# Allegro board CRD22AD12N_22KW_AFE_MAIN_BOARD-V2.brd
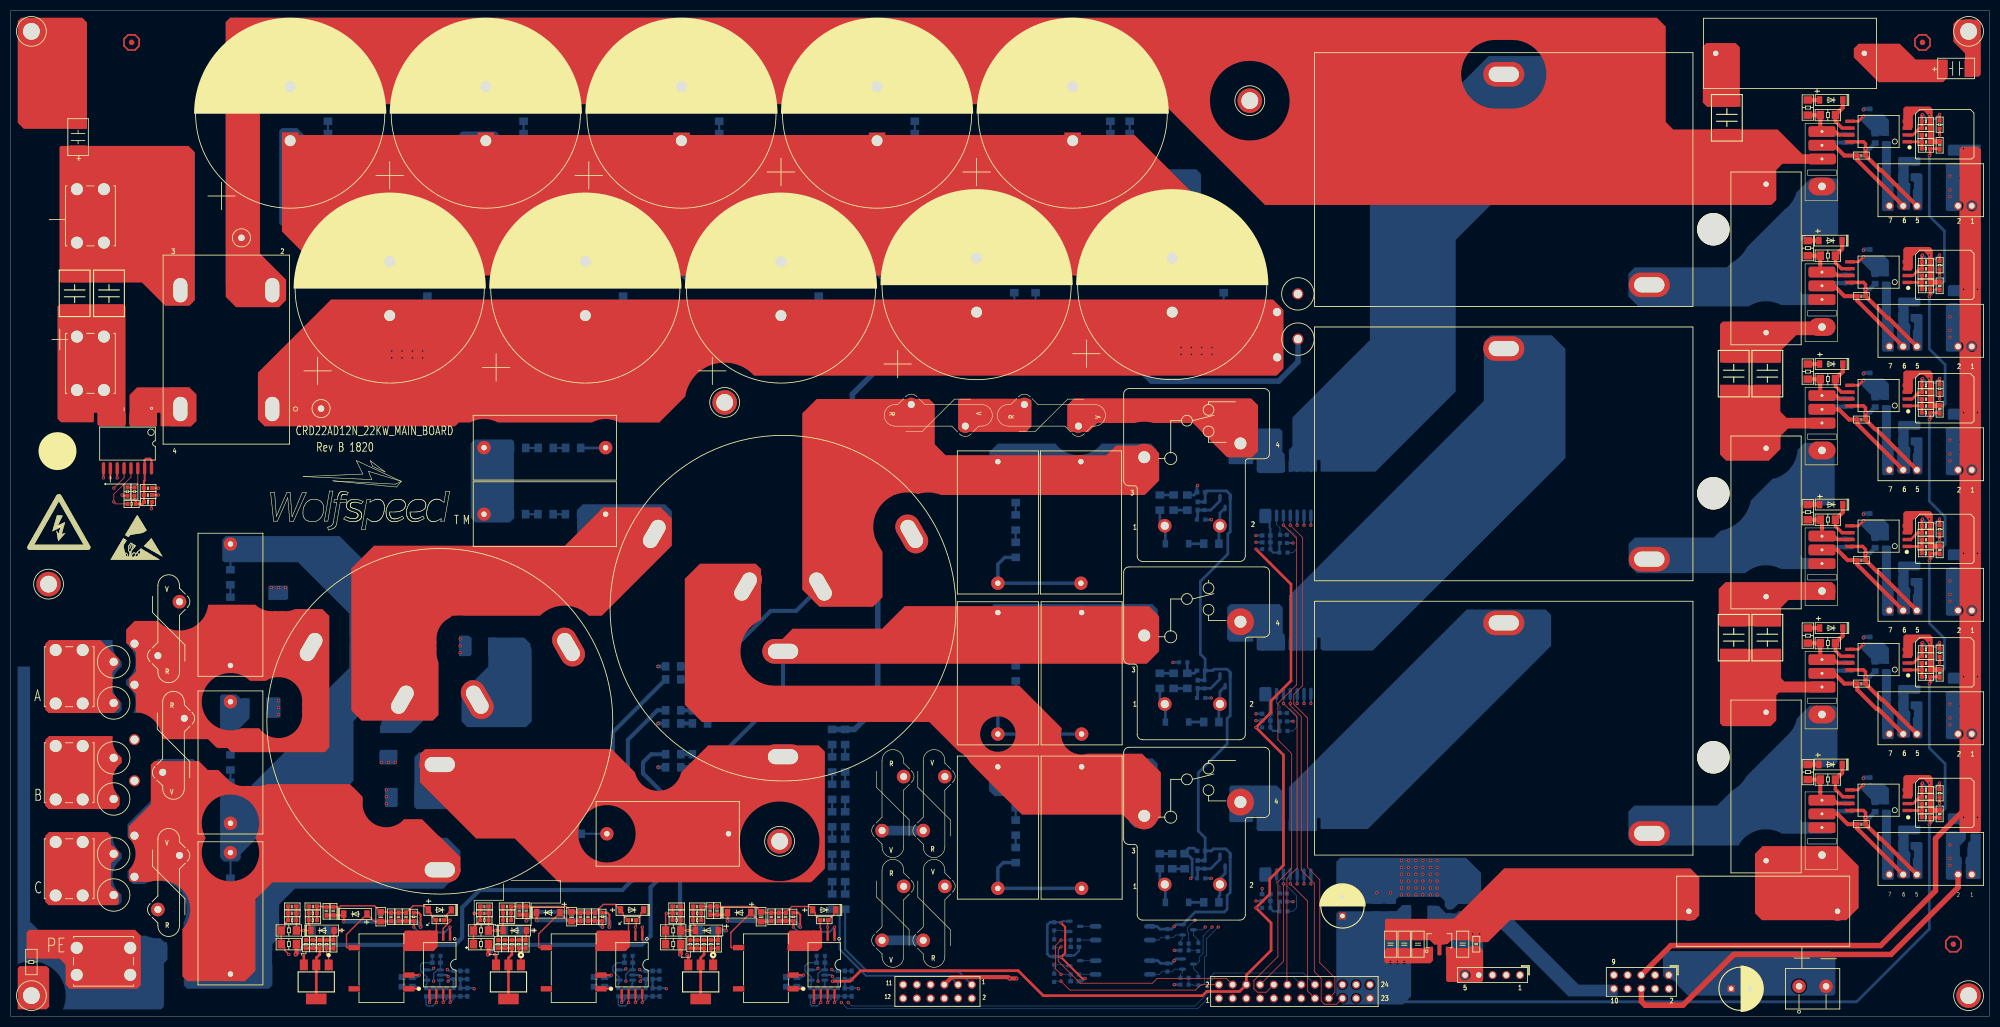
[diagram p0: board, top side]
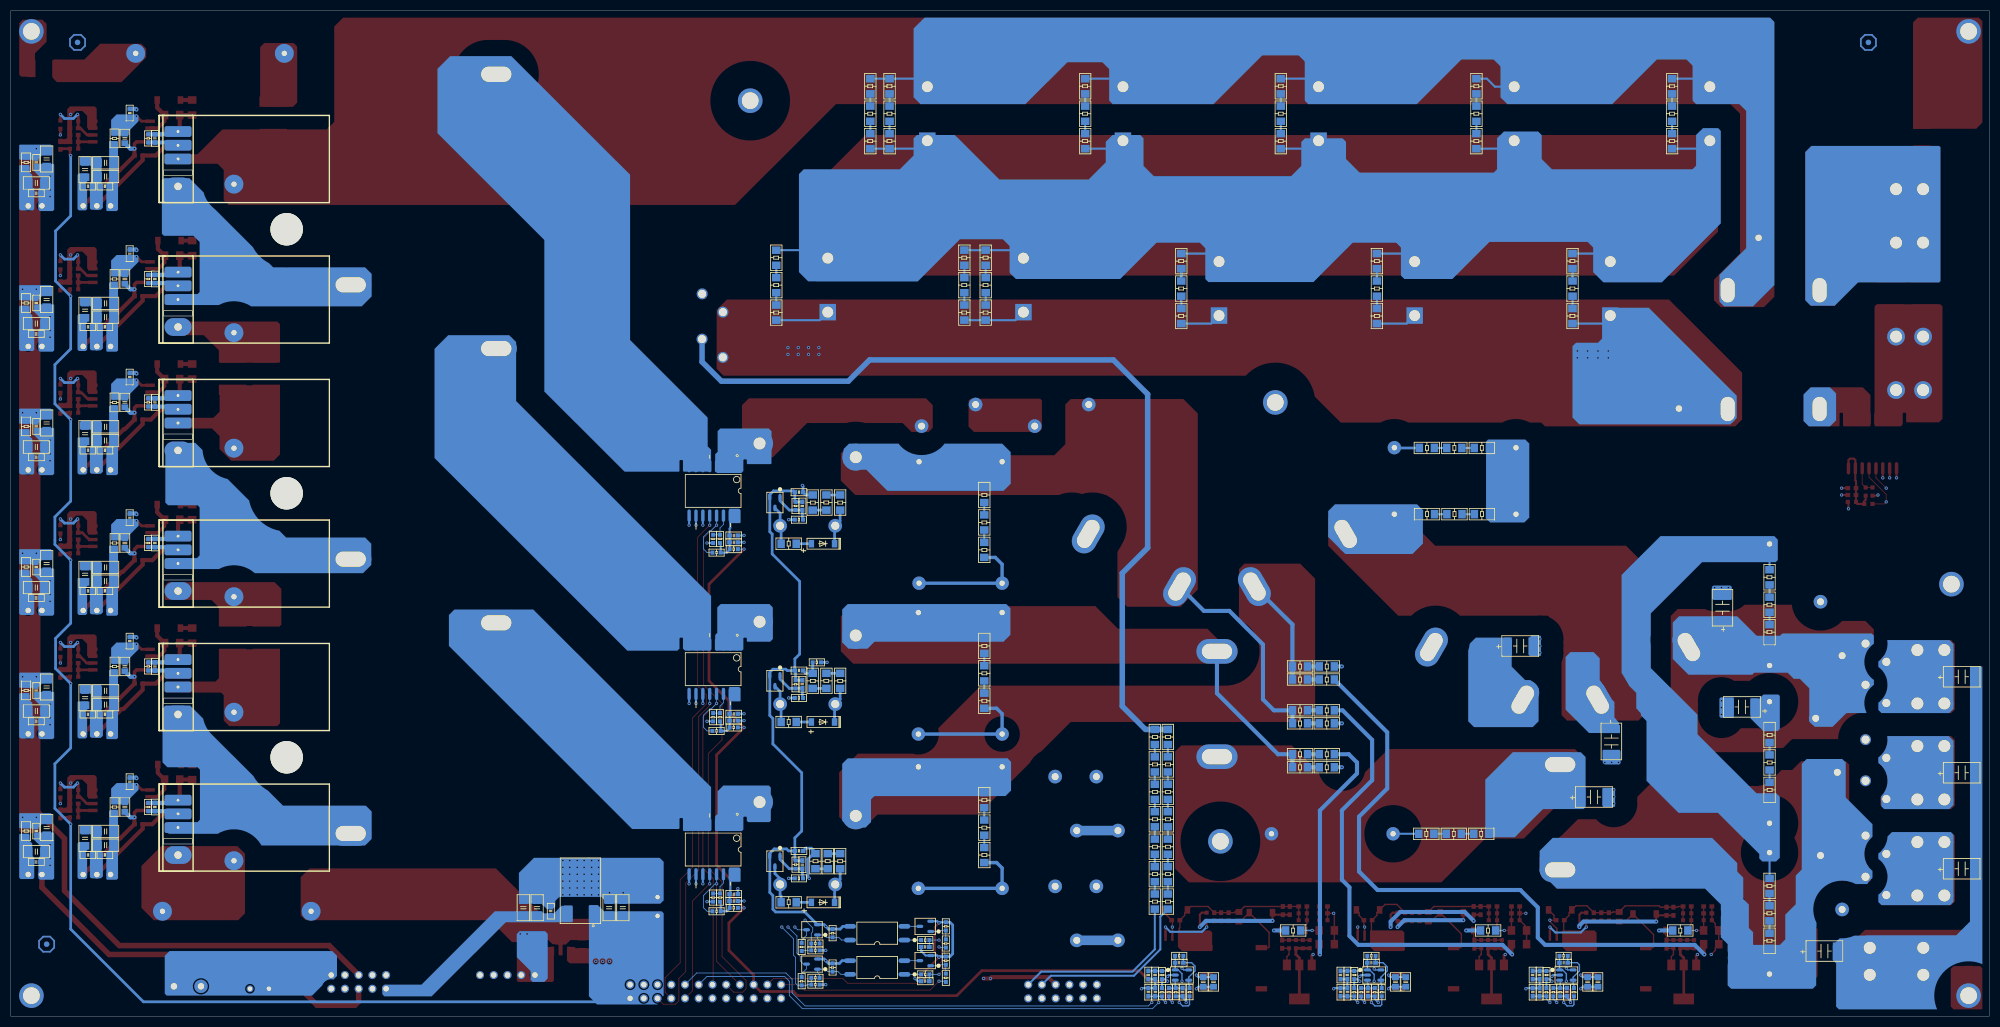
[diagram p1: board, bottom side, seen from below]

Outline 366.04 x 186.19 mm; copper layers: TOP, GND02, POWER03, BOTTOM. Coordinates in mm from the lower left corner of the outline.
Outline path: rectangle 332.45,155.71 337.75,156.71 ; rectangle 332.45,129.67 337.75,130.67 ; rectangle 332.45,106.81 337.75,107.81 ; rectangle 332.45,80.78 337.75,81.78 ; rectangle 332.45,57.92 337.75,58.92 ; rectangle 332.45,31.88 337.75,32.88 ; 0,186.19 0,0 366.04,0 366.04,186.19 0,186.19

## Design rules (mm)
net group DI: nets AGND GGND GND_EARTH IGND PGND
net group GAO: nets AC_LA AC_LA1 AC_LAP AC_LB AC_LB1 AC_LBP AC_LC AC_LC1 AC_LCP LA LB LC N17896613 N17896948 N17898200 N17898311 N17908016 N17908018 N17908020 N17908062 N17916066 N17916108 N17916243 N17920487 VPFC
net group R_DI: nets N17911032 N17911109 N17911239 N17911323 N18077724 N18077784 N179113761

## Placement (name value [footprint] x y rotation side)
C1  0.1uF  [C0603]  220.22 30.61 0 bottom
C2  1n  [C0603]  219.58 28.07 270 bottom
C3  0u1  [C0603]  196.85 6.48 0 bottom
C4  0.1uF  [C0603]  220.22 97.03 0 bottom
C5  1n  [C0603]  219.58 94.49 270 bottom
C6  0u1  [C0603]  196.85 12.83 0 bottom
C7  1n  [C0603]  339.36 38.73 270 bottom
C8  1n  [C0603]  339.36 136.53 270 bottom
C9  1n  [C0603]  339.36 87.63 270 bottom
C10  500V 680uF  [ECAP_D35P7_25]  106.3 134.75 90 top
C11  500V 680uF  [ECAP_D35P7_25]  142.49 134.75 90 top
C13  500V 680uF  [ECAP_D35P7_25]  178.69 135.38 90 top
C16  500V 680uF  [ECAP_D35P7_25]  214.88 135.38 90 top
C17  500V 680uF  [ECAP_D35P7_25]  70.1 134.75 90 top
C19  0u1  [C2220]  317.5 166.37 270 top
C20  0u1  [C2220]  318.77 119 270 top
C21  0u1  [C2220]  324.99 119 270 top
C23  500V 680uF  [ECAP_D35P7_25]  124.08 167.13 90 top
C24  500V 680uF  [ECAP_D35P7_25]  160.27 167.13 90 top
C27  500V 680uF  [ECAP_D35P7_25]  51.69 167.13 90 top
C28  500V 680uF  [ECAP_D35P7_25]  87.88 167.13 90 top
C31  500V 680uF  [ECAP_D35P7_25]  196.47 167.13 90 top
C32  0u1  [C2220]  324.99 70.1 270 top
C33  0u1  [C2220]  318.77 70.1 270 top
C34  1n  [C0603]  339.36 162.56 270 bottom
C35  1n  [C0603]  339.36 113.67 270 bottom
C36  1n  [C0603]  339.36 64.77 270 bottom
C37  0.1U  [C0603]  25.4 96.52 0 top
C38  1U  [C0603]  25.4 97.79 0 top
C39  0.1U  [C0603]  232.28 21.34 180 bottom
C40  1U  [C0603]  232.28 22.61 180 bottom
C41  0.1U  [C0603]  232.28 87.76 180 bottom
C42  1U  [C0603]  232.28 89.03 180 bottom
C43  0.1U  [C0603]  232.28 54.74 180 bottom
C44  1U  [C0603]  232.28 56.01 180 bottom
C45  10u  [C1206]  268.61 13.34 270 top
C46  1U  [C0603]  271.14 13.34 270 top
C47  10u  [C1206]  268.68 20.08 270 bottom
C48  1U  [C0603]  266.14 19.45 270 bottom
C49  1u  [C1206]  260.35 13.34 270 top
C50  22u  [C1206]  257.81 13.34 270 top
C51  22u  [C1206]  255.27 13.34 270 top
C52  10u  [C1206]  271.22 20.08 270 bottom
C53  10u  [C1206]  255.34 20.08 270 bottom
C54  10u  [C1206]  252.8 20.08 270 bottom
C55  25V 220uF  [ECAP_D8P3_5]  246.38 20.32 90 top
C56  1uF  [C0603]  348.62 55.88 0 bottom
C57  4u7  [C1206]  348.49 60.25 0 bottom
C58  10uF  [C1206]  348.49 57.71 0 bottom
C59  1uF  [C0603]  348.62 29.85 0 bottom
C60  4u7  [C1206]  348.49 34.21 0 bottom
C61  10uF  [C1206]  348.49 31.67 0 bottom
C62  10uF  [C1206]  359.41 60.96 270 bottom
C63  1uF  [C0603]  361.31 60.33 270 bottom
C64  0u1  [C0603]  361.31 54.61 180 bottom
C65  2u2  [C1206]  361.31 56.52 180 bottom
C66  10uF  [C1206]  359.41 34.92 270 bottom
C67  1uF  [C0603]  361.31 34.29 270 bottom
C68  0u1  [C0603]  361.31 28.57 180 bottom
C69  2u2  [C1206]  361.31 30.48 180 bottom
C70  1uF  [C0603]  351.79 55.88 0 bottom
C71  1uF  [C0603]  351.79 29.85 0 bottom
C72  10uF  [C1206]  352.3 32.94 270 bottom
C73  10uF  [C1206]  352.3 58.98 270 bottom
C74  1uF  [C0603]  348.62 153.67 0 bottom
C75  4u7  [C1206]  348.49 158.04 0 bottom
C76  10uF  [C1206]  348.49 155.5 0 bottom
C77  10uF  [C1206]  348.49 129.46 0 bottom
C78  0u1  [C0603]  361.31 152.4 180 bottom
C79  2u2  [C1206]  361.31 154.31 180 bottom
C80  1uF  [C0603]  348.62 127.64 0 bottom
C81  4u7  [C1206]  348.49 132 0 bottom
C82  10uF  [C1206]  359.41 158.75 270 bottom
C83  1uF  [C0603]  361.31 158.12 270 bottom
C84  10uF  [C1206]  359.41 132.72 270 bottom
C85  1uF  [C0603]  361.31 132.08 270 bottom
C86  0u1  [C0603]  361.31 126.36 180 bottom
C87  2u2  [C1206]  361.31 128.27 180 bottom
C88  1uF  [C0603]  351.79 127.64 0 bottom
C89  1uF  [C0603]  351.79 153.67 0 bottom
C90  10uF  [C1206]  352.3 130.73 270 bottom
C91  10uF  [C1206]  352.3 156.77 270 bottom
C92  1uF  [C0603]  348.62 104.78 0 bottom
C93  4u7  [C1206]  348.49 109.14 0 bottom
C94  10uF  [C1206]  348.49 106.6 0 bottom
C95  10uF  [C1206]  348.49 80.57 0 bottom
C96  0u1  [C0603]  361.31 103.5 180 bottom
C97  2u2  [C1206]  361.31 105.41 180 bottom
C98  1uF  [C0603]  348.62 78.74 0 bottom
C99  4u7  [C1206]  348.49 83.11 0 bottom
C100  10uF  [C1206]  359.41 109.86 270 bottom
C101  1uF  [C0603]  361.31 109.22 270 bottom
C102  10uF  [C1206]  359.41 83.82 270 bottom
C103  1uF  [C0603]  361.31 83.19 270 bottom
C104  0u1  [C0603]  361.31 77.47 180 bottom
C105  2u2  [C1206]  361.31 79.38 180 bottom
C106  1uF  [C0603]  351.79 78.74 0 bottom
C107  1uF  [C0603]  351.79 104.78 0 bottom
C108  10uF  [C1206]  352.3 81.84 270 bottom
C109  10uF  [C1206]  352.3 107.87 270 bottom
C110  25V 220uF  [ECAP_D8P3_5]  320.04 5.08 0 top
C111  2.2u  [C0603]  356.87 135.25 90 top
C112  1U  [C0603]  354.33 137.16 0 top
C113  0.1U  [C0603]  354.33 135.89 0 top
C114  0.33n  [C0603]  354.33 138.43 0 top
C115  2.2u  [C0805]  344.94 136.53 270 bottom
C116  1U  [C0603]  344.05 141.22 90 bottom
C117  1U  [C0603]  342.4 133.35 0 top
C118  2.2u  [C0603]  356.87 161.29 90 top
C119  1U  [C0603]  354.33 163.19 0 top
C120  0.1U  [C0603]  354.33 161.93 0 top
C121  0.33n  [C0603]  354.33 164.47 0 top
C122  2.2u  [C0805]  344.94 162.56 270 bottom
C123  1U  [C0603]  344.05 167.26 90 bottom
C124  1U  [C0603]  342.4 159.38 0 top
C125  2.2u  [C0603]  356.87 37.47 90 top
C126  1U  [C0603]  354.33 39.37 0 top
C127  0.1U  [C0603]  354.33 38.1 0 top
C128  0.33n  [C0603]  354.33 40.64 0 top
C129  2.2u  [C0805]  344.94 38.73 270 bottom
C130  1U  [C0603]  344.05 43.43 90 bottom
C131  1U  [C0603]  342.4 35.56 0 top
C132  2.2u  [C0603]  356.87 63.5 90 top
C133  1U  [C0603]  354.33 65.41 0 top
C134  0.1U  [C0603]  354.33 64.14 0 top
C135  0.33n  [C0603]  354.33 66.67 0 top
C136  2.2u  [C0805]  344.94 64.77 270 bottom
C137  1U  [C0603]  344.05 69.47 90 bottom
C138  1U  [C0603]  342.4 61.59 0 top
C139  2.2u  [C0603]  356.87 86.36 90 top
C140  1U  [C0603]  354.33 88.27 0 top
C141  0.1U  [C0603]  354.33 87 0 top
C142  0.33n  [C0603]  354.33 89.53 0 top
C143  2.2u  [C0805]  344.94 87.63 270 bottom
C144  1U  [C0603]  344.05 92.33 90 bottom
C145  1U  [C0603]  342.4 84.45 0 top
C146  2.2u  [C0603]  356.87 112.39 90 top
C147  1U  [C0603]  354.33 114.3 0 top
C148  0.1U  [C0603]  354.33 113.03 0 top
C149  0.33n  [C0603]  354.33 115.57 0 top
C150  2.2u  [C0805]  344.94 113.67 270 bottom
C151  1U  [C0603]  344.05 118.36 90 bottom
C152  1U  [C0603]  342.4 110.49 0 top
C153  0.1U  [C0603]  83.18 7.62 270 bottom
C154  0.01u  [C0603]  84.45 7.62 270 bottom
C155  4.7u  [C0805]  72.39 6.35 90 bottom
C156  4.7u  [C0805]  74.3 6.35 90 bottom
C157  0.1U  [C0603]  73.15 18.41 270 top
C158  1U  [C0603]  71.75 18.41 270 top
C159  0.1U  [C0603]  58.42 19.43 270 top
C160  1U  [C0603]  59.69 19.43 270 top
C161  4.7u  [C0805]  68.45 18.41 270 top
C162  0.1U  [C0603]  84.46 4.45 90 bottom
C163  0.01u  [C0603]  83.19 4.45 90 bottom
C164  0.1U  [C0603]  70.36 18.41 270 top
C165  0.1U  [C0603]  59.69 13.34 90 top
C166  0.1U  [C0603]  79.38 17.78 180 top
C167  0.1U  [C0603]  52.07 20.32 0 top
C168  DNP  [C0603]  52.07 19.05 0 top
C169  4.7u  [C0805]  109.86 6.35 90 bottom
C170  4.7u  [C0805]  107.95 6.35 90 bottom
C171  0.1U  [C0603]  55.88 20.32 0 top
C172  0.1U  [C0603]  94.11 19.56 270 top
C173  1U  [C0603]  95.38 19.56 270 top
C174  4.7u  [C0805]  103.76 18.41 270 top
C175  0.1U  [C0603]  118.74 7.62 270 bottom
C176  0.01u  [C0603]  120.01 7.62 270 bottom
C177  0.1U  [C0603]  105.41 18.41 270 top
C178  0.1U  [C0603]  120.02 4.45 90 bottom
C179  0.01u  [C0603]  118.75 4.45 90 bottom
C180  0.1U  [C0603]  114.94 17.78 180 top
C181  0.1U  [C0603]  108.08 18.41 270 top
C182  1U  [C0603]  106.81 18.41 270 top
C183  4.7u  [C0805]  145.42 6.35 90 bottom
C184  4.7u  [C0805]  143.51 6.35 90 bottom
C185  0.1U  [C0603]  95.25 13.34 90 top
C186  0.1U  [C0603]  87.63 20.32 0 top
C187  DNP  [C0603]  87.63 19.05 0 top
C188  0.1U  [C0603]  143.38 18.41 270 top
C189  1U  [C0603]  142.11 18.41 270 top
C190  4.7u  [C0805]  138.81 18.41 270 top
C191  0.1U  [C0603]  154.3 7.62 270 bottom
C192  0.01u  [C0603]  155.57 7.62 270 bottom
C193  0.1U  [C0603]  91.82 20.32 0 top
C194  0.1U  [C0603]  140.72 18.41 270 top
C195  0.1U  [C0603]  155.58 4.45 90 bottom
C196  0.01u  [C0603]  154.31 4.45 90 bottom
C197  0.1U  [C0603]  150.5 17.78 180 top
C198  0.1U  [C0603]  129.41 19.56 270 top
C199  1U  [C0603]  130.68 19.56 270 top
C200  0.1U  [C0603]  130.81 13.34 90 top
C201  0.1U  [C0603]  123.19 20.32 0 top
C202  DNP  [C0603]  123.19 19.05 0 top
C203  0.1U  [C0603]  127 20.32 0 top
C204  0u1  [C2220]  11.81 133.86 90 top
C205  0u1  [C2220]  18.16 133.86 90 top
C206  2.2u  [CAPFILM_31_5X12_5MM]  329.18 178.31 0 top
C207  2.2u  [CAPFILM_31_5X12_5MM]  324.23 19.43 180 top
C208  2.2u  [CAPFILM_31_5X12_5MM]  324.76 42.55 90 top
C209  2.2u  [CAPFILM_31_5X12_5MM]  324.76 140.34 90 top
C210  2.2u  [CAPFILM_31_5X12_5MM]  324.76 91.44 90 top
C212  1n  [C0603]  219.58 61.47 270 bottom
C213  0.1uF  [C0603]  220.22 64.01 0 bottom
C214  NA  [C0603]  78.74 9.91 0 bottom
C215  NA  [C0603]  78.11 4.45 270 bottom
C216  NA  [C0603]  114.94 4.45 270 bottom
C217  NA  [C0603]  114.3 9.91 0 bottom
C218  NA  [C0603]  149.22 4.45 270 bottom
C219  NA  [C0603]  149.86 9.91 0 bottom
CL1  6Ts  [CM_4P]  39.88 123.44 90 top
CL1_A1  8u  [LCM1]  79.38 54.61 0 top
CL2_A1  8u  [LCM1]  142.88 75.56 0 top
CON1  Connecter  [THREAD4_9P9X5_1110X920]  10.79 62.87 270 top
CON2  Connecter  [THREAD4_9P9X5_1110X920]  10.79 45.09 270 top
CON3  Connecter  [THREAD4_9P9X5_1110X920]  10.79 27.3 270 top
CON4  Connecter  [THREAD4_9P9X5_1110X920]  17.14 10.16 0 top
CON5  Connecter  [THREAD4_9P9X5_1110X920]  14.73 120.9 90 top
CON6  Connecter  [THREAD4_9P9X5_1110X920]  14.73 148.21 270 top
D1  1N4148W  [SOD-123]  215.77 21.08 180 bottom
D2  1N4148W  [SOD-123]  215.77 87.5 180 bottom
D3  MBR0530TR  [SOD-123]  63.75 18.92 180 top
D4  dnp  [SOD-123]  79.38 19.68 0 top
D5  BAT46W-E3-GSO8  [SOD-123]  57.66 15.88 180 top
D6  MBR0530TR  [SOD-123]  99.44 19.18 180 top
D7  dnp  [SOD-123]  114.94 19.68 0 top
D8  MBR0530TR  [SOD-123]  134.75 19.18 180 top
D9  BAT46W-E3-GSO8  [SOD-123]  93.22 15.88 180 top
D10  dnp  [SOD-123]  150.5 19.68 0 top
D11  BAT46W-E3-GSO8  [SOD-123]  128.78 15.88 180 top
D12  1N4148W  [SOD-123]  215.77 54.48 180 bottom
D13  SL14PL-TP  [SOD-123]  336.69 46.61 0 top
D14  SL14PL-TP  [SOD-123]  336.8 71.88 0 top
D15  SL14PL-TP  [SOD-123]  336.8 169.67 0 top
D16  SL14PL-TP  [SOD-123]  336.68 143.64 0 top
D17  SL14PL-TP  [SOD-123]  336.8 94.74 0 top
D18  SL14PL-TP  [SOD-123]  336.8 120.78 0 top
F1  25A  [FULSE]  22.88 69 180 top
F2  25A  [FULSE]  22.88 61.38 180 top
F3  25A  [FULSE]  22.88 51.22 180 top
F4  25A  [FULSE]  22.88 43.6 180 top
F5  25A  [FULSE]  22.88 33.44 180 top
F6  25A  [FULSE]  22.88 25.82 180 top
F7  25A  [FULSE]  234.3 122.01 0 top
F8  25A  [FULSE]  234.28 130.39 0 top
J1  CON24A  [CON_2MM54_12X2]  237.49 4.57 0 top
J2  CON12A  [CON_2MM54_6X2]  171.45 4.57 180 top
J3  CON2  [CON_5MM_2X1]  333.35 5.53 0 top
J4  CON10A  [CON_2MM54_5X2]  301.68 6.35 180 top
J5  CON5  [CON_2MM54_5X1]  274.14 7.62 180 top
L2  8u  [L71MM]  276.23 53.34 90 top
L3  8u  [L71MM]  276.23 154.94 90 top
L4  8u  [L71MM]  276.23 104.14 90 top
MT1  T1T2  [MTH122]  3.81 3.81 90 top
MT2  T1T2  [MTH122]  362.23 182.38 90 top
MT3  T1T2  [MTH122]  3.81 182.38 90 top
NOREF  #VAL  [unnamed]  359.41 13.34 0 top
NOREF#2  -  [#2]  286.22 103.07 0 top
NOREF#3  -  [#2]  8.88 90.64 0 top
NOREF#4  T1T2  [unnamed]  6.99 80.01 90 top
NOREF#5  T1T2  [unnamed]  142.24 32.38 90 top
NOREF#6  -  [#2]  23.37 87.76 0 top
NOREF#7  T1T2  [unnamed]  132.08 113.66 90 top
NOREF#8  -  [#2]  0 0 0 top
NOREF#9  -  [#2]  8.64 104.65 0 top
NOREF#10  #VAL  [unnamed]  353.69 180.34 0 top
NOREF#11  T1T2  [unnamed]  362.23 3.81 90 top
NOREF#12  #VAL  [unnamed]  22.35 180.34 0 top
NOREF#13  T1T2  [unnamed]  229.23 169.54 90 top
NOREF#14  -  [#2]  0 0 90 top
NOREF#15  #VAL  [unnamed]  22.35 180.34 180 bottom
NOREF#16  #VAL  [unnamed]  353.69 180.34 180 bottom
NOREF#17  -  [unnamed#3]  315.01 145.73 180 bottom
NOREF#18  -  [unnamed#3]  315.01 47.94 180 bottom
NOREF#19  -  [unnamed#3]  315.01 96.84 180 bottom
NOREF#20  #VAL  [unnamed]  359.41 13.34 180 bottom
Q1  2N7002K  [SOT-23]  224.66 28.7 0 bottom
Q2  2N7002K  [SOT-23]  217.8 9.65 90 bottom
Q3  2N7002K  [SOT-23]  196.85 10.29 90 bottom
Q4  2N7002K  [SOT-23]  224.66 95.12 0 bottom
Q5  2N7002K  [SOT-23]  217.8 16 90 bottom
Q6  2N7002K  [SOT-23]  196.85 16.64 90 bottom
Q7  C3M0032120K  [TO-247-4L]  335.1 34.92 90 bottom
Q8  C3M0032120K  [TO-247-4L]  335.1 132.71 90 bottom
Q9  C3M0021120K  [TO-247-4L]  335.1 83.82 90 bottom
Q10  C3M0032120K  [TO-247-4L]  335.1 158.75 90 bottom
Q11  C3M0032120K  [TO-247-4L]  335.1 60.96 90 bottom
Q12  C3M0021120K  [TO-247-4L]  335.1 109.85 90 bottom
Q15  2N7002K  [SOT-23]  224.66 62.1 0 bottom
R1  360K  [R1206]  40.64 71.12 270 bottom
R2  360K  [R1206]  104.01 92.96 0 bottom
R3  360K  [R1206]  185.93 68.58 90 bottom
R4  360K  [R1206]  40.64 76.2 270 bottom
R5  360K  [R1206]  98.93 92.96 0 bottom
R6  360K  [R1206]  185.93 63.5 90 bottom
R7  360K  [R1206]  40.64 81.28 270 bottom
R8  360K  [R1206]  93.85 92.96 0 bottom
R9  360K  [R1206]  185.93 58.42 90 bottom
R10  360K  [R1206]  40.64 52.07 90 bottom
R11  360K  [R1206]  104.04 105.23 0 bottom
R12  360K  [R1206]  185.93 96.52 90 bottom
R13  360K  [R1206]  40.64 46.99 90 bottom
R14  360K  [R1206]  98.96 105.23 0 bottom
R15  360K  [R1206]  185.93 91.44 90 bottom
R16  360K  [R1206]  40.64 41.91 90 bottom
R17  360K  [R1206]  93.88 105.23 0 bottom
R18  360K  [R1206]  185.93 86.36 90 bottom
R19  360K  [R1206]  40.64 13.97 270 bottom
R20  360K  [R1206]  93.98 33.78 180 bottom
R21  360K  [R1206]  185.93 40 90 bottom
R22  360K  [R1206]  40.64 19.05 270 bottom
R23  360K  [R1206]  99.06 33.78 180 bottom
R24  360K  [R1206]  185.93 34.93 90 bottom
R25  360K  [R1206]  40.64 24.13 270 bottom
R26  360K  [R1206]  104.14 33.78 180 bottom
R27  360K  [R1206]  185.93 29.84 90 bottom
R28  220K  [R1206]  127.51 62.36 180 bottom
R29  220K  [R1206]  122.56 62.36 180 bottom
R33  15R  [R1206]  212.6 28.7 90 bottom
R34  15R  [R1206]  214.88 28.7 270 bottom
R35  15R  [R1206]  217.17 28.7 90 bottom
R36  0R  [R0603]  217.17 5.84 0 bottom
R37  220K  [R1206]  127.51 56.64 180 bottom
R38  220K  [R1206]  122.56 56.64 180 bottom
R42  22  [R1206]  222.12 21.08 0 bottom
R43  10k  [R0603]  219.71 6.48 270 bottom
R44  10k  [R0603]  220.85 28.07 90 bottom
R45  220K  [R1206]  127.51 48.51 180 bottom
R46  220K  [R1206]  122.56 48.51 180 bottom
R50  1K  [R0603]  220.22 25.53 0 bottom
R51  10k  [R0603]  217.17 7.11 0 bottom
R52  1K  [R0603]  196.85 7.75 180 bottom
R53  20k  [R0603]  213.99 9.02 270 bottom
R54  15R  [R1206]  212.6 95.12 90 bottom
R55  15R  [R1206]  215.14 95.12 270 bottom
R56  15R  [R1206]  217.68 95.12 90 bottom
R57  0R  [R0603]  217.17 12.19 0 bottom
R58  220R  [R0603]  193.04 7.11 270 bottom
R59  10k  [R0603]  193.04 10.29 270 bottom
R60  22  [R1206]  222.12 87.5 0 bottom
R61  5k  [R0603]  219.71 12.83 270 bottom
R62  10k  [R0603]  220.85 94.49 90 bottom
R63  1K  [R0603]  220.22 91.95 0 bottom
R64  10k  [R0603]  217.17 13.46 0 bottom
R65  1K  [R0603]  196.85 14.1 180 bottom
R66  20k  [R0603]  213.99 15.37 270 bottom
R67  220R  [R0603]  193.04 13.46 270 bottom
R68  10k  [R0603]  193.04 16.64 270 bottom
R69  6R8  [R1206]  336.19 43.81 180 top
R70  6R8  [R1206]  336.19 140.84 180 top
R71  6R8  [R1206]  336.19 91.95 180 top
R72  0R  [R1206]  151.96 51.71 90 bottom
R73  0  [R1206]  154.38 51.71 90 bottom
R74  10k  [R0603]  340.63 38.73 90 bottom
R75  10k  [R0603]  340.63 136.53 90 bottom
R76  10k  [R0603]  340.63 87.63 90 bottom
R77  620K  [R1206]  154.38 46.63 90 bottom
R78  620K  [R1206]  151.96 46.63 90 bottom
R79  620K  [R1206]  154.38 41.55 90 bottom
R80  620K  [R1206]  151.96 41.55 90 bottom
R81  620K  [R1206]  154.38 36.47 90 bottom
R82  6R8  [R1206]  336.19 166.88 180 top
R83  620K  [R1206]  151.96 36.47 90 bottom
R84  620K  [R1206]  154.38 31.39 90 bottom
R85  6R8  [R1206]  336.19 117.98 180 top
R86  6R8  [R1206]  336.19 69.09 180 top
R87  10k  [R0603]  340.63 162.56 90 bottom
R88  10k  [R0603]  340.63 113.67 90 bottom
R89  620K  [R1206]  151.96 31.39 90 bottom
R90  620K  [R1206]  154.38 26.31 90 bottom
R91  10k  [R0603]  340.63 64.77 90 bottom
R92  620K  [R1206]  151.96 26.31 90 bottom
R93  620K  [R1206]  154.38 21.23 90 bottom
R94  620K  [R1206]  151.96 21.23 90 bottom
R95  10R  [R0603]  25.4 95.25 180 top
R96  6.8k  [R0603]  22.86 97.16 90 top
R97  10k  [R0603]  22.35 94.87 180 top
R98  10R  [R0603]  232.28 20.07 0 bottom
R99  6.8k  [R0603]  234.82 21.97 90 bottom
R100  10k  [R0603]  235.46 19.43 0 bottom
R101  1.8k  [R0603]  21.59 97.16 270 top
R102  1.8k  [R0603]  236.09 21.97 270 bottom
R103  10R  [R0603]  232.28 86.49 0 bottom
R104  6.8k  [R0603]  234.82 88.39 90 bottom
R105  10k  [R0603]  235.46 85.85 0 bottom
R106  10R  [R0603]  232.28 53.47 0 bottom
R107  6.8k  [R0603]  234.82 55.37 90 bottom
R108  10k  [R0603]  235.46 52.83 0 bottom
R109  1.8k  [R0603]  236.09 88.39 270 bottom
R110  1.8k  [R0603]  236.09 55.37 270 bottom
R111  1R  [R0805]  363.22 60.33 90 bottom
R112  1R  [R0805]  363.22 34.29 90 bottom
R113  1R  [R0805]  363.22 158.12 90 bottom
R114  1R  [R0805]  363.22 132.08 90 bottom
R115  1R  [R0805]  363.22 109.22 90 bottom
R116  1R  [R0805]  363.22 83.19 90 bottom
R117  10R  [R0603]  354.33 134.62 180 top
R118  100  [R0603]  356.87 139.06 90 top
R119  4.7K  [R0603]  354.33 139.7 0 top
R120  1R  [R0805]  346.85 136.53 270 bottom
R121  10R  [R0603]  354.33 160.66 180 top
R122  100  [R0603]  356.87 165.1 90 top
R123  4.7K  [R0603]  354.33 165.74 0 top
R124  1R  [R0805]  346.85 162.56 270 bottom
R125  10R  [R0603]  354.33 36.83 180 top
R126  100  [R0603]  356.87 41.27 90 top
R127  4.7K  [R0603]  354.33 41.91 0 top
R128  1R  [R0805]  346.85 38.73 270 bottom
R129  10R  [R0603]  354.33 62.87 180 top
R130  100  [R0603]  356.87 67.31 90 top
R131  4.7K  [R0603]  354.33 67.95 0 top
R132  1R  [R0805]  346.85 64.77 270 bottom
R133  10R  [R0603]  354.33 85.72 180 top
R134  100  [R0603]  356.87 90.17 90 top
R135  1R  [R0805]  346.85 87.63 270 bottom
R136  4.7K  [R0603]  354.33 90.81 0 top
R137  10R  [R0603]  354.33 111.76 180 top
R138  100  [R0603]  356.87 116.2 90 top
R139  4.7K  [R0603]  354.33 116.84 0 top
R140  1R  [R0805]  346.85 113.67 270 bottom
R141  4.7  [R0603]  81.92 7.62 90 bottom
R142  4.7  [R0603]  74.55 18.41 270 top
R143  4.7  [R0603]  81.91 4.45 270 bottom
R144  10k  [R0603]  79.37 4.45 270 bottom
R145  10k  [R0603]  80.65 4.45 90 bottom
R146  220K  [R1206]  51.44 13.34 180 top
R147  47K  [R0603]  58.42 13.34 270 top
R148  470R  [R0603]  55.88 13.34 270 top
R149  100R  [R0603]  54.61 13.34 270 top
R150  100R  [R0603]  57.15 13.34 270 top
R151  10k  [R0603]  76.84 4.45 90 bottom
R152  1.5K  [R1206]  51.44 15.88 180 top
R153  DNP  [R0603]  52.07 17.78 180 top
R154  10k  [R0603]  78.74 11.18 0 bottom
R155  100R  [R0603]  55.88 17.78 180 top
R156  DNP  [R0603]  55.88 19.05 180 top
R157  4.7  [R0603]  117.48 7.62 90 bottom
R158  4.7  [R0603]  109.47 18.41 90 top
R159  4.7  [R0603]  117.47 4.45 270 bottom
R160  10k  [R0603]  113.66 4.45 270 bottom
R161  10k  [R0603]  116.21 4.45 90 bottom
R162  10k  [R0603]  112.39 4.45 90 bottom
R163  220K  [R1206]  87 13.34 180 top
R164  10k  [R0603]  114.3 11.18 0 bottom
R165  47K  [R0603]  93.98 13.34 270 top
R166  470R  [R0603]  91.44 13.34 270 top
R167  100R  [R0603]  90.17 13.34 270 top
R168  100R  [R0603]  92.71 13.34 270 top
R169  1.5K  [R1206]  87 15.88 180 top
R170  DNP  [R0603]  87.63 17.78 180 top
R171  4.7  [R0603]  144.78 18.41 270 top
R172  4.7  [R0603]  153.04 7.62 90 bottom
R173  10k  [R0603]  150.49 4.45 270 bottom
R174  4.7  [R0603]  153.03 4.45 270 bottom
R175  100R  [R0603]  91.82 17.78 180 top
R176  DNP  [R0603]  91.82 19.05 180 top
R177  10k  [R0603]  151.77 4.45 90 bottom
R178  10k  [R0603]  147.96 4.45 90 bottom
R179  10k  [R0603]  149.86 11.18 0 bottom
R181  220K  [R1206]  122.56 13.34 180 top
R183  47K  [R0603]  129.54 13.34 270 top
R184  470R  [R0603]  127 13.34 270 top
R185  100R  [R0603]  125.73 13.34 270 top
R186  100R  [R0603]  128.27 13.34 270 top
R187  1.5K  [R1206]  122.56 15.88 180 top
R188  DNP  [R0603]  123.19 17.78 180 top
R189  100R  [R0603]  127 17.78 180 top
R190  DNP  [R0603]  127 19.05 180 top
R191  0R  [R0603]  216.92 65.53 0 bottom
R198  10k  [R0603]  220.85 61.47 90 bottom
R199  15R  [R1206]  212.6 62.1 90 bottom
R200  15R  [R1206]  217.68 62.1 90 bottom
R201  1K  [R0603]  220.22 58.93 0 bottom
R202  15R  [R1206]  215.14 62.1 270 bottom
R203  22  [R1206]  222.12 54.48 0 bottom
R204  200K  [R1206]  189.61 135.38 270 bottom
R205  200K  [R1206]  224.41 135.38 270 bottom
R206  200K  [R1206]  189.61 130.3 270 bottom
R207  200K  [R1206]  224.41 130.3 270 bottom
R208  200K  [R1206]  189.61 140.46 270 bottom
R209  200K  [R1206]  224.41 140.46 270 bottom
R210  200K  [R1206]  207.01 162.05 270 bottom
R211  200K  [R1206]  58.67 162.05 270 bottom
R212  200K  [R1206]  207.01 167.13 270 bottom
R213  200K  [R1206]  58.67 167.13 270 bottom
R214  200K  [R1206]  207.01 172.21 270 bottom
R215  200K  [R1206]  58.67 172.21 270 bottom
R216  200K  [R1206]  77.09 134.75 270 bottom
R217  200K  [R1206]  113.28 134.75 270 bottom
R218  200K  [R1206]  77.09 129.67 270 bottom
R219  200K  [R1206]  77.09 139.83 270 bottom
R220  200K  [R1206]  113.28 129.67 270 bottom
R221  200K  [R1206]  113.28 139.83 270 bottom
R222  200K  [R1206]  94.87 162.05 270 bottom
R223  200K  [R1206]  167.26 162.05 270 bottom
R224  200K  [R1206]  167.26 167.13 270 bottom
R225  200K  [R1206]  94.87 167.13 270 bottom
R226  200K  [R1206]  94.87 172.21 270 bottom
R227  200K  [R1206]  167.26 172.21 270 bottom
R228  200K  [R1206]  185.67 135.38 270 bottom
R229  200K  [R1206]  185.67 130.3 270 bottom
R230  200K  [R1206]  185.67 140.46 270 bottom
R231  200K  [R1206]  149.48 134.75 270 bottom
R232  200K  [R1206]  149.48 129.67 270 bottom
R233  200K  [R1206]  149.48 139.83 270 bottom
R234  200K  [R1206]  203.45 162.05 270 bottom
R235  200K  [R1206]  203.45 167.13 270 bottom
R236  200K  [R1206]  203.45 172.21 270 bottom
R237  200K  [R1206]  131.06 162.05 270 bottom
R238  200K  [R1206]  131.06 167.13 270 bottom
R239  200K  [R1206]  131.06 172.21 270 bottom
R240  220K  [R1206]  57.15 15.88 180 bottom
R241  220K  [R1206]  92.71 15.88 180 bottom
R242  220K  [R1206]  128.78 15.88 180 bottom
R243  220K  [R1206]  122.56 54.23 180 bottom
R244  220K  [R1206]  122.56 46.1 180 bottom
R245  220K  [R1206]  122.56 64.77 180 bottom
R258  10R  [R1206]  332.49 45.21 90 top
R259  10R  [R1206]  332.49 70.48 90 top
R260  10R  [R1206]  332.49 168.28 90 top
R261  10R  [R1206]  332.49 142.24 90 top
R262  10R  [R1206]  332.49 93.34 90 top
R263  10R  [R1206]  332.49 119.38 90 top
R264  220K  [R1206]  127.51 54.23 180 bottom
R265  220K  [R1206]  127.51 46.1 180 bottom
R266  220K  [R1206]  127.51 64.77 180 bottom
R267  NA  [R1206]  3.81 10.03 270 top
RLY1  832HA-1A-F-C-12VDC  [T9SV1K15-12]  218.6 32.03 0 top
RLY2  832HA-1A-F-C-12VDC  [T9SV1K15-12]  218.6 98.45 0 top
RLY3  832HA-1A-F-C-12VDC  [T9SV1K15-12]  218.6 65.43 0 top
RV1  NTC  [NTC_OD20MM]  163.19 39.37 90 top
RV2  NTC  [NTC_OD20MM]  170.81 39.37 270 top
RV3  NTC  [NTC_OD20MM]  171.6 111.28 180 top
RV4  NTC  [NTC_OD20MM]  192.53 111.28 180 top
RV5  NTC  [NTC_OD20MM]  170.81 19.05 270 top
RV6  NTC  [NTC_OD20MM]  163.19 19.05 90 top
TP1  T1T2  [TH47_CR98]  57.4 112.52 0 top
TP2  T1T2  [TH47_CR98]  42.67 144.15 0 top
U1  -  [TCLT1003]  205.74 9.02 0 bottom
U2  -  [TCLT1003]  205.74 15.37 0 bottom
U3  ACS733  [SOICW-16]  21.59 106.05 270 top
U4  ACS733  [SOICW-16]  236.09 30.86 270 bottom
U5  ACS733  [SOICW-16]  236.09 97.28 270 bottom
U6  ACS733  [SOICW-16]  236.09 64.26 270 bottom
U7  MC78L05F-TP  [SOT-89-3L]  264.31 13.52 90 top
U8  LF50ABDT-TR  [TO252AB]  260.59 26.15 180 bottom
U9  R15P21503D  [G1212S_2W11]  355.2 54.38 180 top
U10  R15P21503D  [G1212S_2W11]  355.2 28.34 180 top
U11  R15P21503D  [G1212S_2W11]  355.2 152.17 180 top
U12  R15P21503D  [G1212S_2W11]  355.2 126.13 180 top
U13  R15P21503D  [G1212S_2W11]  355.2 103.27 180 top
U14  R15P21503D  [G1212S_2W11]  355.2 77.24 180 top
U15  UCC5350MC  [SOIC8_DWV]  345.58 137.79 180 top
U16  UCC5350MC  [SOIC8_DWV]  345.58 163.83 180 top
U17  UCC5350MC  [SOIC8_DWV]  345.58 40.01 180 top
U18  UCC5350MC  [SOIC8_DWV]  345.58 66.04 180 top
U19  UCC5350MC  [SOIC8_DWV]  345.58 88.9 180 top
U20  UCC5350MC  [SOIC8_DWV]  345.58 114.94 180 top
U21  LT3092EST_SOT223_5  [SOT223_3]  56.52 6.35 180 top
U22  PS_B0505XT  [SMD-5]  68.58 8.89 90 top
U23  ACPL-C870-500E  [SSO-8]  79.37 9.53 180 top
U24  MCP6031  [SOT23-5]  78.23 7.62 270 bottom
U25  PS_B0505XT  [SMD-5]  104.14 8.89 90 top
U26  ACPL-C870-500E  [SSO-8]  114.93 9.53 180 top
U27  MCP6031  [SOT23-5]  113.79 7.62 270 bottom
U28  LT3092EST_SOT223_5  [SOT223_3]  92.08 6.35 180 top
U29  PS_B0505XT  [SMD-5]  139.7 8.89 90 top
U30  ACPL-C870-500E  [SSO-8]  150.49 9.53 180 top
U31  MCP6031  [SOT23-5]  149.35 7.62 270 bottom
U32  LT3092EST_SOT223_5  [SOT223_3]  127.64 6.35 180 top
VAR1  S20K625  [MOV_OD21P5MM_PI10MM_PINV3P3MM]  29.21 71.76 270 top
VAR2  S20K625  [MOV_OD21P5MM_PI10MM_PINV3P3MM]  30.1 50.16 90 top
VAR3  S20K625  [MOV_OD21P5MM_PI10MM_PINV3P3MM]  29.21 24.77 270 top
XC1  2.2uF  [CAPFILM_26_5X12MM]  40.64 76.2 90 top
XC2  2.2uF  [CAPFILM_26_5X12MM]  98.81 92.96 180 top
XC3  3.3uF  [CAPFILM_26_5X15MM]  182.63 63.5 270 top
XC4  2.2uF  [CAPFILM_26_5X12MM]  40.64 46.99 270 top
XC5  2.2uF  [CAPFILM_26_5X12MM]  98.81 105.28 180 top
XC6  3.3uF  [CAPFILM_26_5X15MM]  182.63 91.44 270 top
XC7  2.2uF  [CAPFILM_26_5X12MM]  40.64 19.05 90 top
XC8  2.2uF  [CAPFILM_26_5X12MM]  121.54 33.78 180 top
XC9  3.3uF  [CAPFILM_26_5X15MM]  182.63 34.92 270 top
XC10  3.3uF  [CAPFILM_26_5X15MM]  198.12 34.92 270 top
XC11  3.3uF  [CAPFILM_26_5X15MM]  197.99 91.44 270 top
XC12  3.3uF  [CAPFILM_26_5X15MM]  198.12 63.5 270 top
YC1  220P  [C1812]  5.08 62.87 180 bottom
YC2  220P  [C1812]  49.35 75.64 90 bottom
YC3  220p  [C1812]  69.9 50.88 270 bottom
YC4  220P  [C1812]  5.08 45.09 180 bottom
YC5  220P  [C1812]  45.75 57.28 0 bottom
YC6  220p  [C1812]  86.77 68.55 180 bottom
YC7  220P  [C1812]  5.08 27.3 180 bottom
YC8  220p  [C1812]  73.13 40.59 180 bottom
YC9  220P  [C1812]  30.48 12.06 180 bottom
YC10  220P  [C1812]  359.92 175.51 0 top
YC11  220P  [C1812]  12.45 162.81 90 top

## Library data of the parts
C1-C9 C19-C21 C32-C54 C56-C109 C111-C210 C212-C219 XC1-XC12 YC1 YC2 YC4 YC5 YC7 YC9-YC11 = CAP NP: User Part Number: HAMP; Tolerance: #TOL
C10 C11 C13 C16 C17 C23 C24 C27 C28 C31 = CAP POL: Tolerance: #TOL; User Part Number: HAMP
C55 C110 = CAP POL: User Part Number: HAMP; Tolerance: #TOL
CL1 = TRNSFMR 67125450_0: User Part Number: HAMP; Tolerance: #TOL
CL1_A1 CL2_A1 = 126LNS_5: Tolerance: #TOL; User Part Number: HAMP
CON1-CON6 = Connecter: Tolerance: #TOL; User Part Number: HAMP
D1 D2 D12-D18 = DIODE_0: Tolerance: #TOL; User Part Number: HAMP
D3 D5 D6 D8 D9 D11 = BAS21/SOT_1: Tolerance: #TOL; User Part Number: HAMP
D4 D7 D10 = DIODE ZENER_0: Tolerance: #TOL; User Part Number: HAMP
F1-F8 = FUSE_0: User Part Number: HAMP; Tolerance: #TOL
J1 = CON24A: User Part Number: HAMP; Tolerance: #TOL
J2 = CON12A: User Part Number: HAMP; Tolerance: #TOL
J3 = CON2: User Part Number: HAMP; Tolerance: #TOL
J4 = CON10A: User Part Number: HAMP; Tolerance: #TOL
J5 = CON5: User Part Number: HAMP; Tolerance: #TOL
L2-L4 = 126LNS_1: Tolerance: #TOL; User Part Number: HAMP
MT1-MT3 = CON1_2: User Part Number: HAMP; Tolerance: #TOL
NOREF NOREF#5 NOREF#10-NOREF#12 NOREF#15 NOREF#16 NOREF#20 = -: Tolerance: #TOL; User Part Number: HAMP
NOREF#4 NOREF#7 NOREF#13 = -: User Part Number: HAMP; Tolerance: #TOL
Q1-Q6 Q15 = 2N7002/SOT: User Part Number: HAMP; Tolerance: #TOL
Q7-Q12 = C3M0065090J_4: Tolerance: #TOL; User Part Number: HAMP
R1-R27 = R_2: User Part Number: HAMP; Tolerance: #TOL
R28 R29 R33-R38 R42-R46 R50-R68 R72 R73 R77-R81 R83 R84 R89 R90 R92-R94 R111-R116 R118 R119 R122 R123 R126 R127 R130 R131 R134 R136 R138 R139 R141-R179 R181 R183-R191 R198-R245 R264-R267 = RESISTOR: User Part Number: HAMP; Tolerance: #TOL
R69-R71 R74-R76 R82 R85-R88 R91 R95-R110 R117 R120 R121 R124 R125 R128 R129 R132 R133 R135 R137 R140 R258-R263 = R: User Part Number: HAMP; Tolerance: #TOL
RLY1-RLY3 = RELAY SPST_1: User Part Number: HAMP; Tolerance: #TOL
RV1-RV6 VAR1-VAR3 = VARISTOR: User Part Number: HAMP; Tolerance: #TOL
TP1 TP2 = CON1_2: Tolerance: #TOL; User Part Number: HAMP
U1 U2 = LEU169_TCLT1003_SOP-4L: User Part Number: HAMP; Tolerance: #TOL
U3-U6 = MCR1101_0: User Part Number: HAMP; Tolerance: #TOL
U7 U8 = MC78L05F-TP: User Part Number: HAMP; Tolerance: #TOL
U9-U14 = E1212S-2WR2_3: User Part Number: HAMP; Tolerance: #TOL
U15-U20 = UCC5350MC: Tolerance: #TOL; User Part Number: HAMP
U21 U28 U32 = LT3092EST_SOT223_5: Tolerance: #TOL; User Part Number: HAMP
U22 U25 U29 = PS_B0505XT: Tolerance: #TOL; User Part Number: HAMP
U23 U26 U30 = 24C16BT-I/SN_3: User Part Number: HAMP; Tolerance: #TOL
U24 U27 U31 = MCP6031: Tolerance: #TOL; User Part Number: HAMP
YC3 YC6 YC8 = CAP: User Part Number: HAMP; Tolerance: #TOL

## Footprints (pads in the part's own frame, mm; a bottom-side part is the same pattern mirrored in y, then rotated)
C0603
  rect 0.889x0.787 smd: 1(-0.76,0) 2(0.76,0)
C0805
  rect 1.092x1.27 smd: 1(-0.89,0) 2(0.89,0)
C1206
  rect 1.397x1.6 smd: 1(-1.4,0) 2(1.4,0)
C1812
  rect 1.499x3.2 smd: 1(-2.3,0) 2(2.3,0)
C2220
  rect 1.905x5.08 smd: 1(-3,0) 2(3,0)
CAPFILM_26_5X12MM
  round 2.489 hole 0.991: 1(-11.25,0) 2(11.25,0)
CAPFILM_26_5X15MM
  round 2.489 hole 0.991: 1(-11.25,0) 2(11.25,0)
CAPFILM_31_5X12_5MM
  round 3.505 hole 0.991: 1(-13.75,0) 2(13.75,0)
CM_4P
  oval 5.5x3 hole 4.5x2.6: 1(-11,-8.5) 2(11,-8.5) 3(11,8.5) 4(-11,8.5)
CON_2MM54_5X1
  round 1.499 hole 1.016: 1(-5.08,0) 2(-2.54,0) 3(0,0) 4(2.54,0) 5(5.08,0)
CON_2MM54_5X2
  round 1.499 hole 1.016: 1(-5.08,-1.27) 2(-5.08,1.27) 3(-2.54,-1.27) 4(-2.54,1.27) 5(0,-1.27) 6(0,1.27) 7(2.54,-1.27) 8(2.54,1.27) 9(5.08,-1.27) 10(5.08,1.27)
CON_2MM54_6X2
  round 1.499 hole 0.991: 1(-6.35,-1.27) 2(-6.35,1.27) 3(-3.81,-1.27) 4(-3.81,1.27) 5(-1.27,-1.27) 6(-1.27,1.27) 7(1.27,-1.27) 8(1.27,1.27) 9(3.81,-1.27) 10(3.81,1.27) 11(6.35,-1.27) 12(6.35,1.27)
CON_2MM54_12X2
  round 1.499 hole 0.991: 1(-13.97,-1.27) 2(-13.97,1.27) 3(-11.43,-1.27) 4(-11.43,1.27) 5(-8.89,-1.27) 6(-8.89,1.27) 7(-6.35,-1.27) 8(-6.35,1.27) 9(-3.81,-1.27) 10(-3.81,1.27) 11(-1.27,-1.27) 12(-1.27,1.27) 13(1.27,-1.27) 14(1.27,1.27) 15(3.81,-1.27) 16(3.81,1.27) 17(6.35,-1.27) 18(6.35,1.27) 19(8.89,-1.27) 20(8.89,1.27) 21(11.43,-1.27) 22(11.43,1.27) 23(13.97,-1.27) 24(13.97,1.27)
CON_5MM_2X1
  round 2.489 hole 1.194: 1(-2.5,0) 2(2.5,0)
ECAP_D8P3_5
  rect 1.27x1.27 hole 0.813: 1(-1.75,0)
  round 1.27 hole 0.813: 2(1.75,0)
ECAP_D35P7_25
  rect 3.048x3.048 hole 2.007: 1(-5,0)
  round 3.048 hole 2.007: 2(5,0)
FULSE
  round 2.032 hole 1.499: 1(3.85,3.375) 2(0,0)
G1212S_2W11
  round 1.499 hole 1.016: 1(-7.62,2.1) 2(-5.08,2.1) 5(2.54,2.1) 6(5.08,2.1) 7(7.62,2.1)
L71MM
  oval 4.572x7.62 hole 2.794x5.588: 1(-19.5,-26.924) 3(19.5,0)
LCM1
  oval 7.62x4.572 hole 5.588x2.794: 1(0,-27.5) 2(0,-8)
  oval 4.572x7.62 hole 2.794x5.588 rot 30: 3(23.816,13.75) 4(6.928,4)
  oval 4.572x7.62 hole 2.794x5.588 rot 150: 5(-23.816,13.75) 6(-6.928,4)
MOV_OD21P5MM_PI10MM_PINV3P3MM
  round 2.54 hole 1.295: 1(-5,2) 2(5,-2)
MTH122
  round 4.572 hole 3.099: 1(0,0)
NTC_OD20MM
  round 2.54 hole 1.295: 1(-5,2) 2(5,-2)
R0603
  rect 0.762x0.762 smd: 1(-0.76,0) 2(0.76,0)
R0805
  rect 0.991x1.194 smd: 1(-1,0) 2(1,0)
R1206
  rect 1.397x1.6 smd: 1(-1.4,0) 2(1.4,0)
SMD-5
  rect 0.991x2.108 smd: 1(-3.81,-5.042) 2(-1.27,-5.042) 3(3.81,-5.042) 4(3.81,5.042) 5(-3.81,5.042)
SOD-123
  rect 1.02x1.4 smd: 1(-2.15,0) 2(2.15,0)
SOIC8_DWV
  rect 1.778x0.635 smd: 1(-5.3,1.905) 2(-5.3,0.635) 3(-5.3,-0.635) 4(-5.3,-1.905) 5(5.3,-1.905) 6(5.3,-0.635) 7(5.3,0.635) 8(5.3,1.905)
SOICW-16
  oval 2.286x0.635 smd: 1(-4.578,4.445) 2(-4.578,3.175) 3(-4.578,1.905) 4(-4.578,0.635) 5(-4.578,-0.635) 6(-4.578,-1.905) 7(-4.578,-3.175) 8(-4.578,-4.445) 9(4.578,-4.445) 10(4.578,-3.175) 11(4.578,-1.905) 12(4.578,-0.635) 13(4.578,0.635) 14(4.578,1.905) 15(4.578,3.175) 16(4.578,4.445)
SOT23-5
  oval 0.61x1.321 smd: 1(-0.95,-1.25) 2(0,-1.25) 3(0.95,-1.25) 4(0.95,1.25) 5(-0.95,1.25)
SOT223_3
  rect 1.499x2.007 smd: 1(-2.3,-3.15) 2(0,-3.15) 3(2.3,-3.15)
  rect 3.81x2.007 smd: 4(0,3.15)
SOT-23
  oval 0.61x1.27 smd: 1(-0.95,-1.01) 2(0.95,-1.01) 3(0,1.01)
SOT-89-3L
  rect 3.404x2.007 smd: (1.45,0)
  rect 1.6x0.61 smd: 1(-1.45,1.5) 3(-1.45,-1.5)
  rect 2.007x0.711 smd: 2(-1.25,0)
SSO-8
  rect 0.457x1.905 smd: 1(-1.905,-5.373) 2(-0.635,-5.373) 3(0.635,-5.373) 4(1.905,-5.373) 5(1.905,5.373) 6(0.635,5.373) 7(-0.635,5.373) 8(-1.905,5.373)
T9SV1K15-12
  round 2.54 hole 1.499: 1(-5.1,-7.625) 2(5.1,-7.625)
  round 5.004 hole 2.21: 3(-8.9,5.075) 4(8.9,7.625)
TCLT1003
  oval 2.184x0.889 smd: 1(-5.025,1.27) 2(-5.025,-1.27) 3(5.025,-1.27) 4(5.025,1.27)
TH47_CR98
  round 2.489 hole 1.194: 1(0,0)
THREAD4_9P9X5_1110X920
  round 3.302 hole 2.21: 1(4.95,2.5) 2(-4.95,2.5) 3(-4.95,-2.5) 4(4.95,-2.5)
TO252AB
  rect 1.6x2.997 smd: 1(2.3,-7.16) 3(-2.3,-7.16)
  rect 6.706x6.706 smd: 2(0,-0.51)
TO-247-4L
  oval 3.302x5.004 hole 1.397: 1(-5.08,0)
  custom 0.5x0.5 hole 1.346x1.702: 2(0,0) 3(2.54,0) 4(5.08,0)
unnamed
  round 1.016 smd: 1(0,0)
unnamed#3
  round 5.994 hole 5.994 unplated: (0,0)

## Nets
-3V_PFCHA: C71.2 C72.2 C129.2 C131.2 U10.5(-VOUT) U17.8(VEE2)
-3V_PFCHB: C88.2 C90.2 C115.2 C117.2 U12.5(-VOUT) U15.8(VEE2)
-3V_PFCHC: C106.2 C108.2 C143.2 C145.2 U14.5(-VOUT) U19.8(VEE2)
-3V_PFCLA: C70.2 C73.2 C136.2 C138.2 U9.5(-VOUT) U18.8(VEE2)
-3V_PFCLB: C89.2 C91.2 C122.2 C124.2 U11.5(-VOUT) U16.8(VEE2)
-3V_PFCLC: C107.2 C109.2 C150.2 C152.2 U13.5(-VOUT) U20.8(VEE2)
AGND: C3.2 C6.2 C37.2 C38.2 C39.2 C40.2 C41.2 C42.2 C43.2 C44.2 C47.1 C48.1 C52.1 C53.1 C54.1 C55.2 C111.2 C112.2 C113.2 C114.2 C118.2 C119.2 C120.2 C121.2 C125.2 C126.2 C127.2 C128.2 C132.2 C133.2 C134.2 C135.2 C139.2 C140.2 C141.2 C142.2 C146.2 C147.2 C148.2 C149.2 C153.2 C154.2 C155.1 C156.1 C162.2 C163.2 C169.1 C170.1 C175.2 C176.2 C178.2 C179.2 C183.1 C184.1 C191.2 C192.2 C195.2 C196.2 C215.2 C216.2 C218.2 J1.13 J1.18 J1.20 J1.21 J1.22 J1.24 J4.9 Q3.2(SOURCE) Q6.2(SOURCE) R59.1 R68.1 R101.2 R102.2 R109.2 R110.2 R119.2 R123.2 R127.2 R131.2 R136.2 R139.2 R144.2 R160.2 R173.2 U3.9(GND) U3.10(GND1) U3.11(PROGRAM) U4.9(GND) U4.10(GND1) U4.11(PROGRAM) U5.9(GND) U5.10(GND1) U5.11(PROGRAM) U6.9(GND) U6.10(GND1) U6.11(PROGRAM) U8.2(GND) U15.3(IN-) U15.4(GND1) U16.3(IN-) U16.4(GND1) U17.3(IN-) U17.4(GND1) U18.3(IN-) U18.4(GND1) U19.3(IN-) U19.4(GND1) U20.3(IN-) U20.4(GND1) U22.1(GND) U23.5(GND2) U24.2(VSS) U25.1(GND) U26.5(GND2) U27.2(VSS) U29.1(GND) U30.5(GND2) U31.2(VSS)
GND_EARTH: CON4.1 CON4.2 CON4.3 CON4.4 R267.1 YC1.2 YC2.2 YC3.2 YC4.2 YC5.2 YC6.2 YC7.2 YC8.2 YC9.2
P6.5V: C47.2 C48.2 C52.2 J4.10 U8.3(VIN)
PGND: C19.2 C20.2 C21.2 C23.2 C24.2 C27.2 C28.2 C31.2 C32.2 C33.2 C45.1 C46.1 C49.1 C50.1 C51.1 C206.2 C207.2 C208.2 C209.2 C210.2 CL1.2(P21) J2.5 J5.5 Q10.2(S) Q11.2(S) Q12.2(S) R214.1 R215.1 R226.1 R227.1 R236.1 R239.1 TP2.1 U7.2(GND) YC10.1
AC_LA: CL2_A1.6 R21.2 R28.1 R266.1 RLY1.3(COMMON) RV1.2 XC9.1 XC10.1
AC_LA1: RLY1.4(NO) RV2.1 U4.1(IP1+) U4.2(IP2+) U4.3(IP3+) U4.4(IP4+)
AC_LA_ADC: J1.15 U4.12(VIOUT)
AC_LA_OC: J1.8 R100.2 U4.13(FAULT)
AC_LA_SAMP: R29.2 R146.1
AC_LAB_G: C157.1 C158.1 C159.1 C160.1 C161.1 C164.1 C166.2 C171.2 D4.1(ANODE) R155.1 R156.1 U22.3(-VO) U23.3(VIN-) U23.4(GND1)
AC_LAB_SENSE: C166.1 C167.1 C168.1 D4.2(CATHODE) R146.2 R152.2 R153.2 U23.2(VIN+)
AC_LAB_SENSE_ADC: C214.2 J2.2 R154.2 U24.1(OUT)
AC_LAP: L2.3 U4.5(IP1-) U4.6(IP2-) U4.7(IP3-) U4.8(IP4-)
AC_LB: CL2_A1.4 R12.2 R37.1 R264.1 RLY2.3(COMMON) RV3.2 XC6.1 XC11.1
AC_LB1: RLY2.4(NO) RV4.1 U5.1(IP1+) U5.2(IP2+) U5.3(IP3+) U5.4(IP4+)
AC_LB_ADC: J1.17 U5.12(VIOUT)
AC_LB_OC: J1.10 R105.2 U5.13(FAULT)
AC_LB_SAMP: R38.2 R163.1
AC_LBC_G: C172.1 C173.1 C174.1 C177.1 C180.2 C181.1 C182.1 C193.2 D7.1(ANODE) R175.1 R176.1 U25.3(-VO) U26.3(VIN-) U26.4(GND1)
AC_LBC_SENSE: C180.1 C186.1 C187.1 D7.2(CATHODE) R163.2 R169.2 R170.2 U26.2(VIN+)
AC_LBC_SENSE_ADC: C217.2 J2.4 R164.2 U27.1(OUT)
AC_LBP: L3.3 U5.5(IP1-) U5.6(IP2-) U5.7(IP3-) U5.8(IP4-)
AC_LC: CL2_A1.2 R3.2 R45.1 R265.1 RLY3.3(COMMON) RV6.2 XC3.1 XC12.1
AC_LC1: RLY3.4(NO) RV5.1 U6.1(IP1+) U6.2(IP2+) U6.3(IP3+) U6.4(IP4+)
AC_LC_ADC: J1.19 U6.12(VIOUT)
AC_LC_OC: J1.12 R108.2 U6.13(FAULT)
AC_LC_SAMP: R46.2 R181.1
AC_LCA_G: C188.1 C189.1 C190.1 C194.1 C197.2 C198.1 C199.1 C203.2 D10.1(ANODE) R189.1 R190.1 U29.3(-VO) U30.3(VIN-) U30.4(GND1)
AC_LCA_SENSE: C197.1 C201.1 C202.1 D10.2(CATHODE) R181.2 R187.2 R188.2 U30.2(VIN+)
AC_LCA_SENSE_ADC: C219.2 J2.6 R179.2 U31.1(OUT)
AC_LCP: L4.3 U6.5(IP1-) U6.6(IP2-) U6.7(IP3-) U6.8(IP4-)
CAN5V_GND: J2.11 J5.2
CAN_5V: J2.12 J5.1
CLAMPHA: C7.1 Q7.4(G) R69.2 R74.2 R258.1 U17.7(CLAMP)
CLAMPHB: C8.1 Q8.4(G) R70.2 R75.2 R261.1 U15.7(CLAMP)
CLAMPHC: C9.1 Q9.4(G) R71.2 R76.2 R262.1 U19.7(CLAMP)
CLAMPLA: C36.1 Q11.4(G) R86.2 R91.2 R259.1 U18.7(CLAMP)
CLAMPLB: C34.1 Q10.4(G) R82.2 R87.2 R260.1 U16.7(CLAMP)
CLAMPLC: C35.1 Q12.4(G) R85.2 R88.2 R263.1 U20.7(CLAMP)
DC_14V_INPUT: C110.1 J3.2 J4.1
GGND: C1.2 C2.1 C4.2 C5.1 C62.2 C63.2 C64.2 C65.2 C66.2 C67.2 C68.2 C69.2 C78.2 C79.2 C82.2 C83.2 C84.2 C85.2 C86.2 C87.2 C96.2 C97.2 C100.2 C101.2 C102.2 C103.2 C104.2 C105.2 C212.1 C213.2 J4.6 Q1.2(SOURCE) Q2.2(SOURCE) Q4.2(SOURCE) Q5.2(SOURCE) Q15.2(SOURCE) R44.2 R53.1 R62.2 R66.1 R198.2 U1.3 U2.3 U9.2(-VIN) U10.2(-VIN) U11.2(-VIN) U12.2(-VIN) U13.2(-VIN) U14.2(-VIN)
IGND: C110.2 J3.1 J4.2
IOUT_ADC: J1.14 U3.12(VIOUT)
LA: CON1.1 CON1.2 CON1.3 CON1.4 F1.1 F2.1 YC1.1
LAB_G: C167.2 C168.2 C171.1 D5.2(CATHODE) R152.1 R153.1 R155.2 R156.2 R240.2
LB: CON2.1 CON2.2 CON2.3 CON2.4 F3.1 F4.1 YC4.1
LBC_G: C186.2 C187.2 C193.1 D9.2(CATHODE) R169.1 R170.1 R175.2 R176.2 R241.2
LC: CON3.1 CON3.2 CON3.3 CON3.4 F5.1 F6.1 YC7.1
LCA_G: C201.2 C202.2 C203.1 D11.2(CATHODE) R187.1 R188.1 R189.2 R190.2 R242.2
OUTPUT_OC: J1.16 R97.2 U3.13(FAULT)
PFC_G_HA: C7.2 C59.2 C60.2 C61.2 C71.1 C72.1 C130.2 C131.1 Q7.3(GS) R74.1 U10.6(COM)
PFC_G_HB: C8.2 C77.2 C80.2 C81.2 C88.1 C90.1 C116.2 C117.1 Q8.3(GS) R75.1 U12.6(COM)
PFC_G_HC: C9.2 C95.2 C98.2 C99.2 C106.1 C108.1 C144.2 C145.1 Q9.3(GS) R76.1 U14.6(COM)
PFC_G_LA: C36.2 C56.2 C57.2 C58.2 C70.1 C73.1 C137.2 C138.1 Q11.3(GS) R91.1 U9.6(COM)
PFC_G_LB: C34.2 C74.2 C75.2 C76.2 C89.1 C91.1 C123.2 C124.1 Q10.3(GS) R87.1 U11.6(COM)
PFC_G_LC: C35.2 C92.2 C93.2 C94.2 C107.1 C109.1 C151.2 C152.1 Q12.3(GS) R88.1 U13.6(COM)
PFCDRVHA: D13.2(K) R69.1 U17.6(OUT)
PFCDRVHB: D16.2(K) R70.1 U15.6(OUT)
PFCDRVHC: D17.2(K) R71.1 U19.6(OUT)
PFCDRVLA: D14.2(K) R86.1 U18.6(OUT)
PFCDRVLB: D15.2(K) R82.1 U16.6(OUT)
PFCDRVLC: D18.2(K) R85.1 U20.6(OUT)
PWM1A: J1.1 R126.1
PWM1B: J1.3 R130.1
PWM1C: J1.5 R118.1
PWM1D: J1.7 R122.1
PWM1E: J1.9 R134.1
PWM1F: J1.11 R138.1
RLYCTRL1: J1.2 R58.2
RLYCTRL2: J1.4 R67.2
VA+5V: C159.2 C160.2 D3.2(CATHODE) R142.1 U21.3(IN)
VB+5V: C181.2 C182.2 D6.2(CATHODE) R158.1 U28.3(IN)
VC+5V: C198.2 C199.2 D8.2(CATHODE) R171.1 U32.3(IN)
VO1+: J2.1 R93.1
VO2+: J2.3 R94.1
VP3.3D: J1.6 R95.1 R98.1 R103.1 R106.1 R141.1 R143.1 R157.1 R159.1 R172.1 R174.1
VP+5V: C3.1 C6.1 C53.2 C54.2 C55.1 C111.1 C118.1 C125.1 C132.1 C139.1 C146.1 C155.2 C156.2 C169.2 C170.2 C183.2 C184.2 J1.23 R52.2 R65.2 R117.1 R121.1 R125.1 R129.1 R133.1 R137.1 U8.1(VOUT) U22.2(VIN) U25.2(VIN) U29.2(VIN)
VP+15V: C62.1 C63.1 C66.1 C67.1 C82.1 C83.1 C84.1 C85.1 C100.1 C101.1 C102.1 C103.1 J4.5 R36.1 R57.1 R111.2 R112.2 R113.2 R114.2 R115.2 R116.2 R191.1
VP+15V_PFCHA: C59.1 C60.1 C61.1 R128.2 U10.7(+VOUT)
VP+15V_PFCHB: C77.1 C80.1 C81.1 R120.2 U12.7(+VOUT)
VP+15V_PFCHC: C95.1 C98.1 C99.1 R135.2 U14.7(+VOUT)
VP+15V_PFCLA: C56.1 C57.1 C58.1 R132.2 U9.7(+VOUT)
VP+15V_PFCLB: C74.1 C75.1 C76.1 R124.2 U11.7(+VOUT)
VP+15V_PFCLC: C92.1 C93.1 C94.1 R140.2 U13.7(+VOUT)
VPFC: C10.1 C11.1 C13.1 C16.1 C17.1 CL1.1(P11) F7.2 F8.2 R206.2 R207.2 R218.2 R220.2 R229.2 R232.2 TP1.1
VS+5V: C49.2 C50.2 C51.2 J2.7 U7.1(VOUT)
VS+15V: C45.2 C46.2 J5.4 U7.3(VIN)
N17200031: C165.1 R147.2 U21.1(SET)
N17200043: C165.2 D5.1(ANODE) R147.1 R148.1 R149.1 R150.1
N17200052: R148.2 R149.2 R150.2 U21.2(OUT) U21.4(OUT1)
N17202885: C185.1 R165.2 U28.1(SET)
N17202901: C185.2 D9.1(ANODE) R165.1 R166.1 R167.1 R168.1
N17202907: R166.2 R167.2 R168.2 U28.2(OUT) U28.4(OUT1)
N17203702: C200.1 R183.2 U32.1(SET)
N17203726: R184.2 R185.2 R186.2 U32.2(OUT) U32.4(OUT1)
N17203738: C200.2 D11.1(ANODE) R183.1 R184.1 R185.1 R186.1
N17207655: C157.2 C158.2 R142.2 U23.1(VDD1)
N17208388: C162.1 C163.1 R143.2 U23.8(VDD2)
N17208484: R145.1 U23.7(VOUT+)
N17208491: R151.1 U23.6(VOUT-)
N17208678: C214.1 R151.2 R154.1 U24.4(-)
N17208781: C153.1 C154.1 R141.2 U24.5(VDD)
N17209770: C172.2 C173.2 R158.2 U26.1(VDD1)
N17209888: C178.1 C179.1 R159.2 U26.8(VDD2)
N17209896: R161.1 U26.7(VOUT+)
N17209898: R162.1 U26.6(VOUT-)
N17209922: C216.1 R160.1 R161.2 U27.3(+)
N17209924: C217.1 R162.2 R164.1 U27.4(-)
N17209942: C175.1 C176.1 R157.2 U27.5(VDD)
N17210692: C188.2 C189.2 R171.2 U30.1(VDD1)
N17210810: C195.1 C196.1 R174.2 U30.8(VDD2)
N17210816: R177.1 U30.7(VOUT+)
N17210820: R178.1 U30.6(VOUT-)
N17210844: C218.1 R173.1 R177.2 U31.3(+)
N17210846: C219.1 R178.2 R179.1 U31.4(-)
N17210864: C191.1 C192.1 R172.2 U31.5(VDD)
N17217934: C215.1 R144.1 R145.2 U24.3(+)
N17223082: C161.2 C164.2 D3.1(ANODE) U22.4(VO)
N17223482: C174.2 C177.2 D6.1(ANODE) U25.4(VO)
N17224001: C190.2 C194.2 D8.1(ANODE) U29.4(VO)
N17453218: C64.1 C65.1 R111.1 U9.1(+VIN)
N17746491: C126.1 C127.1 R125.2 U17.1(VCC1)
N17747250: C128.1 R126.2 R127.1 U17.2(IN+)
N17751858: C129.1 C130.1 R128.1 U17.5(VCC2)
N17896613: CL1_A1.1 F5.2 F6.2 R19.2 VAR2.1 VAR3.1 XC7.1 YC9.1
N17896717: R28.2 R29.1
N17896948: R7.1 R16.1 R25.1 XC1.2 XC4.2 XC7.2
N17897141: R19.1 R22.2
N17897143: R22.1 R25.2
N17898200: CL1_A1.5 F1.2 F2.2 R1.2 VAR1.2 VAR2.2 XC1.1 YC2.1
N17898311: CL1_A1.3 F3.2 F4.2 R10.2 VAR1.1 VAR3.2 XC4.1 YC5.1
N17903019: R10.1 R13.2
N17903021: R13.1 R16.2
N17903179: R1.1 R4.2
N17903181: R4.1 R7.2
N17908016: CL1_A1.2 CL2_A1.1 R20.2 XC8.1 YC8.1
N17908018: CL1_A1.4 CL2_A1.3 R11.2 XC5.1 YC6.1
N17908020: R8.1 R17.1 R26.1 XC2.2 XC5.2 XC8.2
N17908040: R11.1 R14.2
N17908042: R14.1 R17.2
N17908062: CL1_A1.6 CL2_A1.5 R2.2 XC2.1 YC3.1
N17908092: R2.1 R5.2
N17908094: R5.1 R8.2
N17908164: R20.1 R23.2
N17908166: R23.1 R26.2
N17911015: C2.2 Q1.1(GATE) R44.1 R50.1
N17911017: Q2.3(DRAIN) R43.1 R50.2
N17911032: Q1.3(DRAIN) R42.2 RLY1.2(COIL1)
N17911094: C1.1 R35.2 R36.2 R43.2 R51.2
N17911109: D1.2(K) R33.1 RLY1.1(COIL2)
N17911126: R34.2 R35.1
N17911128: R33.2 R34.1
N17911225: C5.2 Q4.1(GATE) R62.1 R63.1
N17911227: Q5.3(DRAIN) R61.1 R63.2 R201.2
N17911239: Q4.3(DRAIN) R60.2 RLY2.2(COIL1)
N17911299: C4.1 R56.2 R57.2 R61.2 R64.2
N17911323: D2.2(K) R54.1 RLY2.1(COIL2)
N17911339: R55.2 R56.1
N17911341: R54.2 R55.1
N17913837: R37.2 R38.1
N17913950: R45.2 R46.1
N17916039: C19.1 C20.1 C21.1 C32.1 C33.1 C206.1 C207.1 C208.1 C209.1 C210.1 F7.1 F8.1 Q7.1(D) Q8.1(D) Q9.1(D) R72.2 R73.2
N17916066: L2.1 Q7.2(S) Q11.1(D)
N17916108: L3.1 Q8.2(S) Q10.1(D)
N17916243: L4.1 Q9.2(S) Q12.1(D)
N17916612: R72.1 R78.2
N17916616: R78.1 R80.2
N17916654: R77.1 R79.2
N17916656: R79.1 R81.2
N17919278: R83.1 R89.2
N17919280: R89.1 R92.2
N17919331: R84.1 R90.2
N17919333: R90.1 R93.2
N17919338: R80.1 R83.2
N17919341: R81.1 R84.2
N17920487: C10.2 C11.2 C13.2 C16.2 C17.2 C23.1 C24.1 C27.1 C28.1 C31.1 R208.1 R209.1 R210.2 R211.2 R219.1 R221.1 R222.2 R223.2 R230.1 R233.1 R234.2 R237.2
N17922701: C112.1 C113.1 R117.2 U15.1(VCC1)
N17922735: C114.1 R118.2 R119.1 U15.2(IN+)
N17922803: C115.1 C116.1 R120.1 U15.5(VCC2)
N17923309: C119.1 C120.1 R121.2 U16.1(VCC1)
N17923353: C121.1 R122.2 R123.1 U16.2(IN+)
N17923421: C122.1 C123.1 R124.1 U16.5(VCC2)
N17924447: C133.1 C134.1 R129.2 U18.1(VCC1)
N17924481: C135.1 R130.2 R131.1 U18.2(IN+)
N17924549: C136.1 C137.1 R132.1 U18.5(VCC2)
N17925295: C140.1 C141.1 R133.2 U19.1(VCC1)
N17925329: C142.1 R134.2 R136.1 U19.2(IN+)
N17925397: C143.1 C144.1 R135.1 U19.5(VCC2)
N17925494: C147.1 C148.1 R137.2 U20.1(VCC1)
N17925544: C149.1 R138.2 R139.1 U20.2(IN+)
N17925612: C150.1 C151.1 R140.1 U20.5(VCC2)
N17927817: C68.1 C69.1 R112.1 U10.1(+VIN)
N17928860: C86.1 C87.1 R114.1 U12.1(+VIN)
N17929090: C78.1 C79.1 R113.1 U11.1(+VIN)
N17930170: C104.1 C105.1 R116.1 U14.1(+VIN)
N17930400: C96.1 C97.1 R115.1 U13.1(+VIN)
N17951662: C39.1 C40.1 R98.2 R99.1 R100.1 U4.15(VCC1) U4.16(VCC)
N17951990: R99.2 R102.1 U4.14(VOC)
N17952680: C41.1 C42.1 R103.2 R104.1 R105.1 U5.15(VCC1) U5.16(VCC)
N17952780: R104.2 R109.1 U5.14(VOC)
N17953229: C43.1 C44.1 R106.2 R107.1 R108.1 U6.15(VCC1) U6.16(VCC)
N17953329: R107.2 R110.1 U6.14(VOC)
N17988040: Q6.1(GATE) R67.1 R68.2
N17988101: Q6.3(DRAIN) U2.2
N17988123: Q5.1(GATE) R64.1 R66.2 U2.4
N17988189: R65.1 U2.1
N17989219: Q3.1(GATE) R58.1 R59.2
N17989262: Q3.3(DRAIN) U1.2
N17989280: Q2.1(GATE) R51.1 R53.2 U1.4
N17989337: R52.1 U1.1
N17992674: R73.1 R77.2
N17992702: R92.1 R94.2
N18031698: CL1.4(P12) U3.1(IP1+) U3.2(IP2+) U3.3(IP3+) U3.4(IP4+)
N18031715: C204.1 C205.1 CON5.1 CON5.2 CON5.3 CON5.4 U3.5(IP1-) U3.6(IP2-) U3.7(IP3-) U3.8(IP4-)
N18031729: C37.1 C38.1 R95.2 R96.1 R97.1 U3.15(VCC1) U3.16(VCC)
N18031813: R96.2 R101.1 U3.14(VOC)
N18060364: C204.2 C205.2 CL1.3(P22) CON6.1 CON6.2 CON6.3 CON6.4 YC11.1
N18077527: C213.1 R191.2 R200.2
N18077715: C212.2 Q15.1(GATE) R198.1 R201.1
N18077724: Q15.3(DRAIN) R203.2 RLY3.2(COIL1)
N18077784: D12.2(K) R199.1 RLY3.1(COIL2)
N18077797: R200.1 R202.2
N18077799: R199.2 R202.1
N18083752: R204.2 R206.1
N18083755: R205.2 R207.1
N18083758: R204.1 R208.2
N18083761: R205.1 R209.2
N18084124: R210.1 R212.2
N18084127: R211.1 R213.2
N18084130: R213.1 R215.2
N18084133: R212.1 R214.2
N18084369: R216.2 R218.1
N18084371: R217.2 R220.1
N18084373: R216.1 R219.2
N18084375: R217.1 R221.2
N18084659: R222.1 R225.2
N18084661: R223.1 R224.2
N18084679: R224.1 R227.2
N18084681: R225.1 R226.2
N18089484: R228.2 R229.1
N18089486: R228.1 R230.2
N18089654: R231.2 R232.1
N18089656: R231.1 R233.2
N18089831: R234.1 R235.2
N18089841: R235.1 R236.2
N18090018: R237.1 R238.2
N18090028: R238.1 R239.2
N18151288: R241.1 R244.2
N18151343: R240.1 R243.2
N18151366: R242.1 R245.2
N18156742: R9.1 R18.1 R27.1 XC3.2 XC6.2 XC9.2 XC10.2 XC11.2 XC12.2
N18156744: R12.1 R15.2
N18156746: R15.1 R18.2
N18156778: R3.1 R6.2
N18156780: R6.1 R9.2
N18156832: R21.1 R24.2
N18156834: R24.1 R27.2
N18158495: MT3.1 YC11.2
N18179724: D13.1(A) R258.2
N18179852: D14.1(A) R259.2
N18179938: D15.1(A) R260.2
N18180027: D16.1(A) R261.2
N18180134: D17.1(A) R262.2
N18180239: D18.1(A) R263.2
N18184240: R243.1 R264.2
N18184278: R244.1 R265.2
N18184299: R245.1 R266.2
N18189276: MT2.1 YC10.2
N18202622: MT1.1 R267.2
N179111791: RV1.1 RV2.2
N179111870: D1.1(A) R42.1
N179113761: RV3.1 RV4.2
N179113920: D2.1(A) R60.1
N180778471: RV5.2 RV6.1
N180778550: D12.1(A) R203.1

Pads without a net: J2 8 9 10; J4 3 4 7 8; J5 3; NOREF 1; NOREF#4 1; NOREF#5 1; NOREF#7 1; NOREF#10 1; NOREF#11 1; NOREF#12 1; NOREF#13 1; NOREF#15 1; NOREF#16 1; NOREF#20 1; U22 5; U25 5; U29 5

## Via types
v1: diameter 0.61, hole 0.305, TOP to BOTTOM, 282 vias

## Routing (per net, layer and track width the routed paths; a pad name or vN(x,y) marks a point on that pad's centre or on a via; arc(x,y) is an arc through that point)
-3V_PFCHA: length 20.8
  TOP w0.635: v1(343.16,36.83) 343.16,37.72 342.78,38.1 U17.8
  TOP w0.762: U10.5 346,32.9 345.82,32.9 C131.2 v1(343.16,36.83)
  BOTTOM w0.762: v1(343.16,36.83) 343.93,36.83 C129.2
-3V_PFCHB: length 20.8
  TOP w0.635: U15.8 342.78,135.89 343.16,135.51 v1(343.16,134.62)
  TOP w0.762: U12.5 347.4,129.29 347.22,129.29 C117.2 v1(343.16,134.62)
  BOTTOM w0.762: C115.2 343.93,134.62 v1(343.16,134.62)
-3V_PFCHC: length 20.7
  TOP w0.635: U19.8 342.62,87 343.16,86.46 v1(343.16,85.72)
  TOP w0.762: v1(343.16,85.72) C145.2 345.32,82.3 345.5,82.3 U14.5
  BOTTOM w0.762: C143.2 343.93,85.72 v1(343.16,85.72)
-3V_PFCLA: length 20.8
  TOP w0.635: v1(343.16,62.87) 343.16,63.76 342.78,64.14 U18.8
  TOP w0.762: U9.5 346.32,58.61 346.14,58.61 C138.2 v1(343.16,62.86)
  BOTTOM w0.762: C136.2 343.93,62.87 v1(343.16,62.87)
-3V_PFCLB: length 20.8
  TOP w0.635: U16.8 342.78,161.93 343.16,161.55 v1(343.16,160.66)
  TOP w0.762: U11.5 346.07,156.66 345.89,156.66 C124.2 343.16,160.65 v1(343.16,160.66)
  BOTTOM w0.762: C122.2 343.93,160.66 v1(343.16,160.66)
-3V_PFCLC: length 20.8
  TOP w0.635: U20.8 342.78,113.03 343.16,112.65 v1(343.16,111.76)
  TOP w0.762: U13.5 345.11,108.72 344.94,108.72 C152.2 v1(343.16,111.76)
  BOTTOM w0.762: v1(343.16,111.76) 343.93,111.76 C150.2
AGND: length 116.1
  TOP w0.381: v1(148.59,2.54) U30.5 ; U23.5 v1(77.47,2.54) ; U26.5 v1(113.03,2.54) ; U3.11 v1(19.68,99.69) ; v1(198.75,6.99) 198.25,6.99 v1(194.31,10.92) 195.07,11.68 195.07,16.51 v1(194.31,17.27) ; U25.1 v1(111.12,5.08) ; U29.1 v1(146.69,5.08) ; v1(20.57,96.52) 20.7,96.4 R101.2 ; U3.9 v1(17.14,99.69) ; U3.10 v1(18.41,99.69) ; C37.2 v1(27.3,96.52) ; C38.2 v1(27.3,97.79) ; v1(75.56,5.08) U22.1
  BOTTOM w0.381: v1(111.12,5.08) 110.74,5.46 C169.1 C170.1 ; C192.2 C191.2 154.3,5.21 C196.2 C195.2 156.72,5.2 v1(156.84,5.08) ; C39.2 v1(230.38,21.34) ; R144.2 C215.2 78.11,3.48 77.47,2.84 v1(77.47,2.54) ; v1(85.72,5.08) 85.6,5.2 C162.2 C163.2 83.18,5.21 C153.2 C154.2 ; C44.2 v1(230.38,56.01) ; U4.11 v1(238,24.51) ; v1(152.02,7.37) 151.76,7.62 U31.2 ; C41.2 v1(230.38,87.76) ; R110.2 v1(237.24,54.61) ; R102.2 v1(237.24,21.21) ; v1(75.56,5.08) 75.18,5.46 C156.1 C155.1 ; U4.9 v1(240.54,24.51) ; C216.2 R160.2 113.67,3.18 v1(113.03,2.54) ; U27.2 116.2,7.62 v1(116.46,7.37) ; R68.1 194.19,17.4 v1(194.31,17.27) 194.63,17.59 Q6.2 ; U5.9 v1(240.54,90.93) ; U6.10 v1(239.27,57.91) ; U6.11 v1(238,57.91) ; R173.2 C218.2 149.22,3.51 148.59,2.87 v1(148.59,2.54) ; C176.2 C175.2 118.74,5.21 C179.2 C178.2 121.16,5.2 v1(121.28,5.08) ; C40.2 v1(231.52,23.62) ; U5.10 v1(239.27,90.93) ; C184.1 C183.1 146.3,5.46 v1(146.69,5.08) ; v1(80.9,7.37) 80.64,7.62 U24.2 ; U4.10 v1(239.27,24.51) ; R109.2 v1(237.24,87.63) ; C42.2 v1(230.38,89.03) ; C3.2 198.25,6.48 v1(198.75,6.99) ; C43.2 v1(230.38,54.74) ; U6.9 v1(240.54,57.91) ; C6.2 197.61,12.06 196.78,11.24 Q3.2 194.63,11.24 v1(194.31,10.92) ; U5.11 v1(238,90.93)
  BOTTOM w0.508: R68.1 192.28,17.4 191.77,16.89 191.77,11.55 192.28,11.05 R59.1 194.19,11.05 v1(194.31,10.92)
  vias: v1(252.73,22.86) v1(255.27,22.86) v1(257.3,28.83) v1(257.3,27.56) v1(257.3,26.29) v1(257.3,25.02) v1(257.3,23.75) v1(257.3,22.48) v1(258.57,28.83) v1(258.57,27.56) v1(258.57,26.29) v1(258.57,25.02) v1(258.57,23.75) v1(258.57,22.48) v1(259.97,28.83) v1(259.97,27.56) v1(259.97,26.29) v1(259.97,25.02) v1(259.97,23.75) v1(259.97,22.48) v1(261.24,28.83) v1(261.24,27.56) v1(261.24,26.29) v1(261.24,25.02) v1(261.24,23.75) v1(261.24,22.48) v1(262.64,28.83) v1(262.64,27.56) v1(262.64,26.29) v1(262.64,25.02) v1(262.64,23.75) v1(262.64,22.48) v1(263.91,28.83) v1(263.91,27.56) v1(263.91,26.29) v1(263.91,25.02) v1(263.91,23.75) v1(263.91,22.48) v1(354.96,167) v1(354.96,140.97) v1(354.96,118.11) v1(354.96,92.08) v1(354.96,69.22) v1(354.96,43.18)
